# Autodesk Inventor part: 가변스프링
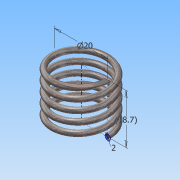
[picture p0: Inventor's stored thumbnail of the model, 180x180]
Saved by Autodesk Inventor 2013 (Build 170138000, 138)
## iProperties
Created: 2019-01
Part Number: 가변스프링
Material: 스테인리스강
Document SubType Name: Modeling
Designer: Administrator
Density: 8.08 g/cm^3
Mass: 7.7937 g
Surface Area: 19.6275 cm^2
Volume: 0.964567 cm^3
Author: Administrator
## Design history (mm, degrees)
sketch "스케치1"
  geometry: L1 (0, 0)-(10, 0); L2 (10, 0)-(10, 18.7); L3 (10, 18.7)-(0, 18.7); L4 (0, 18.7)-(0, 0); C1 r 1 at (10, 0)
  constraints: 8 end point, 2 parallel, 1 centre point, 1 coincident, 1 horizontal, 1 perpendicular
  dimensions: "d0" = 20 diameter of L2 L4; "d2" = 18.7 distance of L1.end L2.end (derived); "d3" = 2 diameter of C1
feature "코일1" pitch "d4" = 10; turns "d6" = 5; dims "d5" = 18.7 (= d2), "d7" = 0, angle "d8" = 90 deg, angle "d9" = 90 deg, "d10" = 0, "d11" = 0
sketch "스케치2"
  geometry: L1 (-11, 0)-(-9, 0) reference; 1 further point
  constraints: 1 horizontal alignment
extrude "돌출1" cut sketch "스케치2" distance "d12" = 10; taper "d13" = 0 deg
node "작업 평면1"
sketch "스케치3"
  geometry: L1 (1, 0)-(-1, 0) reference; 1 further point
  constraints: 1 horizontal alignment
extrude "돌출2" cut sketch "스케치3" distance "d15" = 10; taper "d16" = 0 deg
node "솔리드1"
node "절단 모서리 투영1"
node "절단 모서리 투영2"
other parameters: "d14" = 90 deg
